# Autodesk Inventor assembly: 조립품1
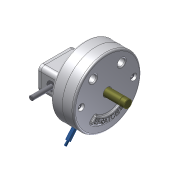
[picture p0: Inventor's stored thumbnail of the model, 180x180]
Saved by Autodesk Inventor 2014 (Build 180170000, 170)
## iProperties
Created: 2015-04
Part Number: 조립품1
Document SubType Name: Assembly
Designer: Administrator
Author: Administrator
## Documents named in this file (15)
- C:\Documents and Settings\Administrator\바탕 화면\350406V1019\조립품1.iam
- C:\Documents and Settings\Administrator\바탕 화면\350406V1019\본체.ipt
- C:\Documents and Settings\Administrator\바탕 화면\350406V1019\커버.ipt
- C:\Documents and Settings\Administrator\바탕 화면\350406V1019\커버2.ipt
- C:\Documents and Settings\Administrator\바탕 화면\350406V1019\M 5 x 12.ipt
- C:\Documents and Settings\Administrator\바탕 화면\350406V1019\M 10 x 35.ipt
- C:\Documents and Settings\Administrator\바탕 화면\350406V1019\축.ipt
- C:\Documents and Settings\Administrator\바탕 화면\350406V1019\슬라이더2.ipt
- C:\Documents and Settings\Administrator\바탕 화면\350406V1019\베어링62_22.ipt
- C:\Documents and Settings\Administrator\바탕 화면\350406V1019\멈춤링.ipt
- C:\Documents and Settings\Administrator\바탕 화면\350406V1019\슬라이더.ipt
- C:\Documents and Settings\Administrator\바탕 화면\350406V1019\평행핀.ipt
- C:\Documents and Settings\Administrator\바탕 화면\350406V1019\슬라이더3.ipt
- C:\Documents and Settings\Administrator\바탕 화면\350406V1019\부시.ipt
- C:\Documents and Settings\Administrator\바탕 화면\350406V1019\스프링.ipt
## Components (5 placed, 3 different names)
1. M 5 x 12:1
2. M 5 x 12:2
3. M 10 x 35:1
4. M 10 x 35:2
5. KS B 1320 B B 5 x  20:1 — 플러쉬:1
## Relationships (1: Flush 1)
- 플러쉬:1 [Flush]: KS B 1320 B B 5 x  20:1
